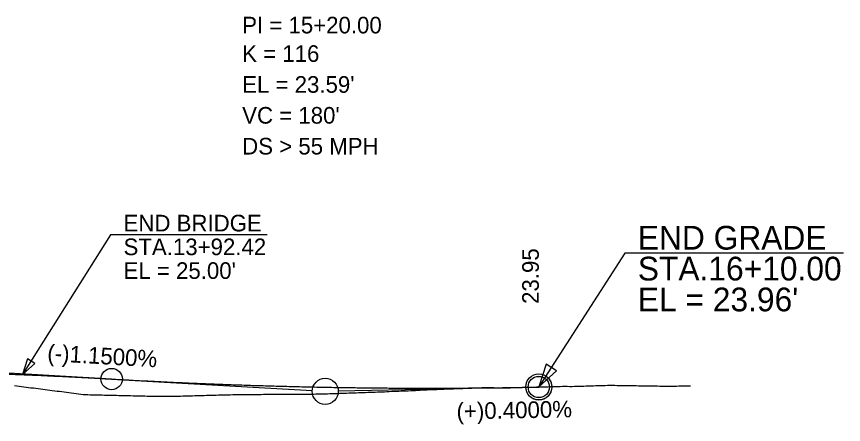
# Model space of a CAD drawing. Extents: x 2534543 to 2535313, y 713006 to 715506.
# Drawn here: x 2534964.8 to 2535313.3, y 714359.8 to 714531.6 of the extents above; entities that cross this region are included whole.
import ezdxf

# ---------------------------------------------------------------- set-up
doc = ezdxf.new("R2010")
doc.units = 0
for name, color, linetype in [('Exist Vertical Profile Ground Line', 7, 'Continuous'), ('Prop Vertical Profile Curve Label', 7, 'Continuous'), ('Prop Vertical Profile Grade', 7, 'Continuous'), ('Prop Vertical Profile Grade Label', 7, 'Continuous'), ('Prop VPI Label', 7, 'Continuous'), ('Scratch_Level_0', 7, 'Continuous'), ('Scratch_Level_2', 7, 'Continuous')]:
    doc.layers.add(name, color=color, linetype=linetype)

msp = doc.modelspace()

# ---------------------------------------------------------------- linework, layer by layer
at = {"layer": 'Exist Vertical Profile Ground Line'}
for points in [[(2534963.89, 714376.18), (2534964.89, 714376.05), (2534965.89, 714375.92), (2534966.89, 714375.8), (2534967.89, 714375.67), (2534968.89, 714375.54), (2534969.89, 714375.41), (2534970.89, 714375.28), (2534971.89, 714375.16), (2534972.89, 714375.03), (2534973.89, 714374.9), (2534974.89, 714374.77)], [(2534974.89, 714374.77), (2534975.89, 714374.64), (2534976.89, 714374.52), (2534977.89, 714374.39), (2534978.89, 714374.26), (2534979.89, 714374.13), (2534980.89, 714374), (2534981.89, 714373.88), (2534982.89, 714373.75), (2534983.89, 714373.62), (2534984.89, 714373.49), (2534985.89, 714373.36), (2534986.89, 714373.24), (2534987.89, 714373.11), (2534988.89, 714372.98), (2534989.89, 714372.85), (2534990.89, 714372.72), (2534991.89, 714372.61), (2534992.89, 714372.48), (2534993.89, 714372.38), (2534994.89, 714372.36), (2534995.89, 714372.33), (2534996.89, 714372.31), (2534997.89, 714372.29), (2534998.89, 714372.26), (2534999.89, 714372.24), (2535000.89, 714372.21), (2535001.89, 714372.19), (2535002.89, 714372.17), (2535003.89, 714372.14), (2535004.89, 714372.12), (2535005.89, 714372.1), (2535006.89, 714372.07), (2535007.89, 714372.05), (2535008.89, 714372.02), (2535009.89, 714372), (2535010.89, 714371.98), (2535011.89, 714371.95), (2535012.89, 714371.93), (2535013.89, 714371.91), (2535014.89, 714371.88), (2535015.89, 714371.86), (2535016.89, 714371.84), (2535017.89, 714371.81), (2535018.89, 714371.79), (2535019.89, 714371.76), (2535020.89, 714371.74), (2535021.89, 714371.72), (2535022.89, 714371.7), (2535023.89, 714371.75), (2535024.89, 714371.74), (2535025.89, 714371.72), (2535026.89, 714371.7), (2535027.89, 714371.68), (2535028.89, 714371.66), (2535029.89, 714371.66), (2535030.89, 714371.69), (2535031.89, 714371.72), (2535032.89, 714371.75), (2535033.89, 714371.77), (2535034.89, 714371.8), (2535035.89, 714371.83), (2535036.89, 714371.86), (2535037.89, 714371.89), (2535038.89, 714371.92), (2535039.89, 714371.94), (2535040.89, 714371.97), (2535041.89, 714372), (2535042.89, 714372.03), (2535043.89, 714372.06), (2535044.89, 714372.08), (2535045.89, 714372.11), (2535046.89, 714372.14), (2535047.89, 714372.16), (2535048.89, 714372.19), (2535049.89, 714372.22), (2535050.89, 714372.24), (2535051.89, 714372.27), (2535052.89, 714372.29), (2535053.89, 714372.32), (2535054.89, 714372.34), (2535055.89, 714372.37), (2535056.89, 714372.39), (2535057.89, 714372.42), (2535058.89, 714372.43), (2535059.89, 714372.44), (2535060.89, 714372.45), (2535061.89, 714372.45), (2535062.89, 714372.46), (2535063.89, 714372.46), (2535064.89, 714372.47), (2535065.89, 714372.47), (2535066.89, 714372.48), (2535067.89, 714372.48), (2535068.89, 714372.49), (2535069.89, 714372.49), (2535070.89, 714372.5), (2535071.89, 714372.5), (2535072.89, 714372.5), (2535073.89, 714372.51), (2535074.89, 714372.51)], [(2535074.89, 714372.51), (2535075.89, 714372.52), (2535076.89, 714372.52), (2535077.89, 714372.53), (2535078.89, 714372.53), (2535079.89, 714372.54), (2535080.89, 714372.54), (2535081.89, 714372.55), (2535082.89, 714372.55), (2535083.89, 714372.56), (2535084.89, 714372.56), (2535085.89, 714372.56), (2535086.89, 714372.58), (2535087.89, 714372.6), (2535088.89, 714372.62), (2535089.89, 714372.62), (2535090.89, 714372.63), (2535091.89, 714372.65), (2535092.89, 714372.67), (2535093.89, 714372.7), (2535094.89, 714372.73), (2535095.89, 714372.76), (2535096.89, 714372.8), (2535097.89, 714372.83), (2535098.89, 714372.87), (2535099.89, 714372.9), (2535100.89, 714372.94), (2535101.89, 714372.97), (2535102.89, 714373), (2535103.89, 714373.04), (2535104.89, 714373.07), (2535105.89, 714373.11), (2535106.89, 714373.14), (2535107.89, 714373.18), (2535108.89, 714373.21), (2535109.89, 714373.25), (2535110.89, 714373.28), (2535111.89, 714373.32), (2535112.89, 714373.35), (2535113.89, 714373.38), (2535114.89, 714373.42), (2535115.89, 714373.45), (2535116.89, 714373.49), (2535117.89, 714373.52), (2535118.89, 714373.56), (2535119.89, 714373.59), (2535120.89, 714373.64), (2535121.89, 714373.72), (2535122.89, 714373.76), (2535123.89, 714373.8), (2535124.89, 714373.83), (2535125.89, 714373.86), (2535126.89, 714373.9), (2535127.89, 714373.93), (2535128.89, 714373.96), (2535129.89, 714374), (2535130.89, 714374.03), (2535131.89, 714374.06), (2535132.89, 714374.11), (2535133.89, 714374.19), (2535134.89, 714374.27), (2535135.89, 714374.35), (2535136.89, 714374.39), (2535137.89, 714374.43), (2535138.89, 714374.47), (2535139.89, 714374.51), (2535140.89, 714374.55), (2535141.89, 714374.59), (2535142.89, 714374.63), (2535143.89, 714374.67), (2535144.89, 714374.71), (2535145.89, 714374.74), (2535146.89, 714374.78), (2535147.89, 714374.82), (2535148.89, 714374.86), (2535149.89, 714374.9), (2535150.89, 714374.93), (2535151.89, 714374.97), (2535152.89, 714375.01), (2535153.89, 714375.05), (2535154.89, 714375.08), (2535155.89, 714375.12), (2535156.89, 714375.16), (2535157.89, 714375.19), (2535158.89, 714375.23), (2535159.89, 714375.27), (2535160.89, 714375.3), (2535161.89, 714375.34), (2535162.89, 714375.37), (2535163.89, 714375.41), (2535164.89, 714375.4), (2535165.89, 714375.33), (2535166.89, 714375.26), (2535167.89, 714375.19), (2535168.89, 714375.19), (2535169.89, 714375.21), (2535170.89, 714375.24), (2535171.89, 714375.27), (2535172.89, 714375.29), (2535173.89, 714375.32), (2535174.89, 714375.34)], [(2535174.89, 714375.34), (2535175.89, 714375.37), (2535176.89, 714375.4), (2535177.89, 714375.42), (2535178.89, 714375.45), (2535179.89, 714375.48), (2535180.89, 714375.5), (2535181.89, 714375.53), (2535182.89, 714375.55), (2535183.89, 714375.58), (2535184.89, 714375.61), (2535185.89, 714375.63), (2535186.89, 714375.66), (2535187.89, 714375.69), (2535188.89, 714375.71), (2535189.89, 714375.74), (2535190.89, 714375.77), (2535191.89, 714375.8), (2535192.89, 714375.82), (2535193.89, 714375.85), (2535194.89, 714375.86), (2535195.89, 714375.86), (2535196.89, 714375.86), (2535197.89, 714375.85), (2535198.89, 714375.85), (2535199.89, 714375.88), (2535200.89, 714375.91), (2535201.89, 714375.94), (2535202.89, 714375.97), (2535203.89, 714375.99), (2535204.89, 714376.02), (2535205.89, 714376.05), (2535206.89, 714376.08), (2535207.89, 714376.11), (2535208.89, 714376.14), (2535209.89, 714376.16), (2535210.89, 714376.19), (2535211.89, 714376.22), (2535212.89, 714376.25), (2535213.89, 714376.28), (2535214.89, 714376.32), (2535215.89, 714376.3), (2535216.89, 714376.29), (2535217.89, 714376.27), (2535218.89, 714376.25), (2535219.89, 714376.24), (2535220.89, 714376.22), (2535221.89, 714376.2), (2535222.89, 714376.19), (2535223.89, 714376.17), (2535224.89, 714376.15), (2535225.89, 714376.14), (2535226.89, 714376.12), (2535227.89, 714376.11), (2535228.89, 714376.09), (2535229.89, 714376.07), (2535230.89, 714376.06), (2535231.89, 714376.04), (2535232.89, 714376.03), (2535233.89, 714376.01), (2535234.89, 714376), (2535235.89, 714375.98), (2535236.89, 714375.96), (2535237.89, 714375.95), (2535238.89, 714375.93), (2535239.89, 714375.92), (2535240.89, 714375.9), (2535241.89, 714375.94), (2535242.89, 714375.98), (2535243.89, 714376.02), (2535244.89, 714376.06), (2535245.89, 714376.07), (2535246.89, 714376.05), (2535247.89, 714376.03), (2535248.81, 714376.02)]]:
    msp.add_lwpolyline(points, dxfattribs=at)
at = {"layer": 'Prop Vertical Profile Curve Label'}
for centre in [(2535004.89, 714378.93), (2535004.89, 714378.93), (2535184.89, 714375.61), (2535184.89, 714375.56)]:
    msp.add_circle(centre, 4.5, dxfattribs=at)
at = {"layer": 'Prop Vertical Profile Grade'}
for points in [[(2534824.89, 714382.31), (2534828.49, 714382.37), (2534832.09, 714382.44), (2534835.69, 714382.5), (2534839.29, 714382.55), (2534842.89, 714382.6), (2534846.49, 714382.64), (2534850.09, 714382.67), (2534853.69, 714382.7), (2534857.29, 714382.73), (2534860.89, 714382.75), (2534864.49, 714382.76), (2534868.09, 714382.77), (2534871.69, 714382.77), (2534875.29, 714382.77), (2534878.89, 714382.76), (2534882.49, 714382.74), (2534886.09, 714382.72), (2534889.69, 714382.7), (2534893.29, 714382.67), (2534896.89, 714382.63), (2534900.49, 714382.59), (2534904.09, 714382.54), (2534907.69, 714382.49), (2534911.29, 714382.43), (2534914.89, 714382.36), (2534918.49, 714382.29), (2534922.09, 714382.22), (2534925.69, 714382.13), (2534929.29, 714382.05), (2534932.89, 714381.95), (2534936.49, 714381.86), (2534940.09, 714381.75), (2534943.69, 714381.64), (2534947.29, 714381.53), (2534950.89, 714381.41), (2534954.49, 714381.28), (2534958.09, 714381.15), (2534961.69, 714381.01), (2534965.29, 714380.87), (2534968.89, 714380.72), (2534972.49, 714380.57), (2534976.09, 714380.41), (2534979.69, 714380.24), (2534983.29, 714380.07), (2534986.89, 714379.9), (2534990.49, 714379.71), (2534994.09, 714379.53), (2534997.69, 714379.33), (2535001.29, 714379.13), (2535004.89, 714378.93)], [(2535004.89, 714378.93), (2535008.49, 714378.73), (2535012.09, 714378.53), (2535015.69, 714378.33), (2535019.29, 714378.15), (2535022.89, 714377.96), (2535026.49, 714377.79), (2535030.09, 714377.62), (2535033.69, 714377.45), (2535037.29, 714377.29), (2535040.89, 714377.14), (2535044.49, 714376.99), (2535048.09, 714376.85), (2535051.69, 714376.71), (2535055.29, 714376.58), (2535058.89, 714376.45), (2535062.49, 714376.33), (2535066.09, 714376.22), (2535069.69, 714376.11), (2535073.29, 714376), (2535076.89, 714375.91), (2535080.49, 714375.81), (2535084.09, 714375.73), (2535087.69, 714375.64), (2535091.29, 714375.57), (2535094.89, 714375.5), (2535098.49, 714375.43), (2535102.09, 714375.37), (2535105.69, 714375.32), (2535109.29, 714375.27), (2535112.89, 714375.23), (2535116.49, 714375.19), (2535120.09, 714375.16), (2535123.69, 714375.14), (2535127.29, 714375.12), (2535130.89, 714375.1), (2535134.49, 714375.09), (2535138.09, 714375.09), (2535141.69, 714375.09), (2535145.29, 714375.1), (2535148.89, 714375.11), (2535152.49, 714375.13), (2535156.09, 714375.16), (2535159.69, 714375.19), (2535163.29, 714375.22), (2535166.89, 714375.26), (2535170.49, 714375.31), (2535174.09, 714375.36), (2535177.69, 714375.42), (2535181.29, 714375.49), (2535184.89, 714375.56)]]:
    msp.add_spline(points, degree=3, dxfattribs=at)
at = {"layer": 'Prop VPI Label'}
for p, q in [((2535004.89, 714378.93), (2534920.38, 714383.79)), ((2535004.89, 714378.93), (2535089.4, 714374.07)), ((2535184.89, 714375.56), (2535100.39, 714373.87))]:
    msp.add_line(p, q, dxfattribs=at)
for centre in [(2535184.89, 714375.61), (2535184.89, 714375.56), (2535094.89, 714373.76)]:
    msp.add_circle(centre, 5.5, dxfattribs=at)
at = {"layer": 'Scratch_Level_2'}
for p, q in [((2535070.43, 714439.6), (2535009.9, 714439.6)), ((2535313.26, 714431.94), (2535226.61, 714431.94))]:
    msp.add_line(p, q, dxfattribs=at)
for points in [[(2535009.9, 714439.6), (2535004.34, 714439.6), (2534967.31, 714380.79)], [(2535226.61, 714431.94), (2535221.17, 714431.94), (2535184.86, 714375.61)]]:
    msp.add_lwpolyline(points, dxfattribs=at)
for points in [[(2534969.38, 714387.47), (2534967.31, 714380.79), (2534972.45, 714385.54)], [(2535187.92, 714385.13), (2535184.86, 714375.61), (2535192.27, 714382.32)]]:
    msp.add_lwpolyline(points, close=True, dxfattribs=at)

# ---------------------------------------------------------------- texts
at = {"layer": 'Prop Vertical Profile Curve Label'}
for s, p in [('K = 116', (2535059.89, 714512.49)), ("VC = 180'", (2535059.89, 714486.49)), ('DS > 55 MPH', (2535059.89, 714473.49))]:
    msp.add_text(s, height=7, dxfattribs=at).set_placement(p)
at = {"layer": 'Prop Vertical Profile Grade Label'}
for s, rotation, p in [('(-)1.1500%', 356.7091, (2534977.64, 714386.51)), ('(+)0.4000%', 1.1458, (2535150.28, 714361.86))]:
    msp.add_text(s, height=7, rotation=rotation, dxfattribs=at).set_placement(p)
at = {"layer": 'Prop VPI Label'}
for s, p in [('PI = 15+20.00', (2535059.89, 714524.49)), ("EL = 23.59'", (2535059.89, 714499.49))]:
    msp.add_text(s, height=7, dxfattribs=at).set_placement(p)
at = {"layer": 'Scratch_Level_0'}
msp.add_text('23.95', height=7, rotation=90, dxfattribs=at).set_placement((2535184.89, 714410.56))
at = {"layer": 'Scratch_Level_2'}
for s, height, p in [('END BRIDGE', 7, (2535009.9, 714441.1)), ('END GRADE', 10, (2535226.61, 714433.44)), ('STA.13+92.42', 7, (2535009.9, 714431.1)), ('STA.16+10.00', 10, (2535226.61, 714420.44)), ("EL = 25.00'", 7, (2535009.9, 714421.1)), ("EL = 23.96'", 10, (2535226.61, 714407.44))]:
    msp.add_text(s, height=height, rotation=0, dxfattribs=at).set_placement(p)

doc.saveas('drawing.dxf')
